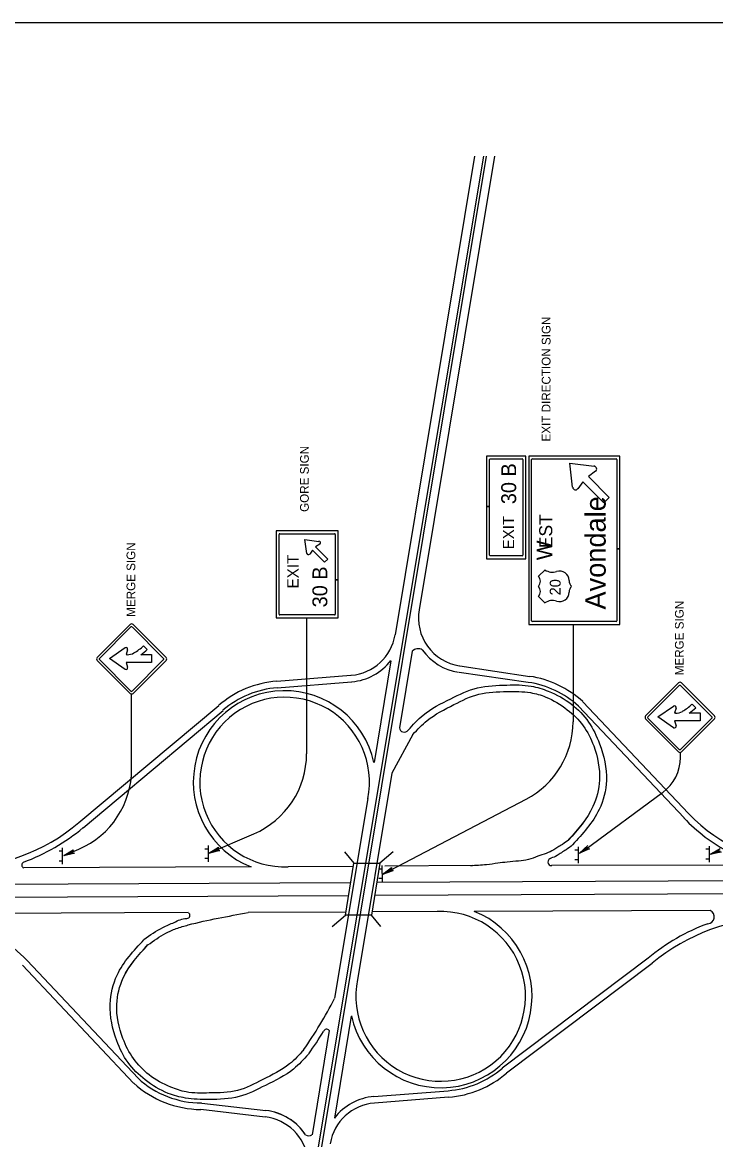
# Model space of a CAD drawing. Extents: x 644898 to 648326, y 298294 to 300670.
# Drawn here: x 645925.8 to 646164.6, y 299676.7 to 300061.5 of the extents above; entities that cross this region are included whole.
import ezdxf

# ---------------------------------------------------------------- set-up
doc = ezdxf.new("R2010")
doc.units = 0
doc.layers.add('1', color=7, linetype='Continuous')
doc.layers.add('2', color=7, linetype='Continuous')

msp = doc.modelspace()

# ---------------------------------------------------------------- linework, layer by layer
at = {"layer": '1'}
msp.add_line((645779.32, 300061.49), (646565.32, 300061.49), dxfattribs=at)
at = {"layer": '2'}
for p, q in [((646084.57, 300015.38), (646006.07, 299544.51)), ((646085.57, 300015.38), (646007.2, 299544.51)), ((646081.57, 300015.38), (646054.2, 299850.51)), ((646088.45, 300015.38), (646062.45, 299859.13)), ((646081.57, 300015.38), (646081.57, 300015.38)), ((646099.2, 299912.13), (646085.7, 299912.13)), ((646085.7, 299912.13), (646085.7, 299894.74)), ((646086.7, 299894.74), (646086.7, 299910.88)), ((646086.95, 299911.13), (646097.95, 299911.13)), ((646098.2, 299910.88), (646098.2, 299878.01)), ((646099.2, 299876.76), (646099.2, 299912.13)), ((646131.57, 299912.13), (646100.2, 299912.13)), ((646100.2, 299912.13), (646100.2, 299854.13)), ((646101.2, 299855.38), (646101.2, 299910.88)), ((646101.45, 299911.13), (646130.32, 299911.13)), ((646115.32, 299901.38), (646114.32, 299909.63)), ((646114.32, 299909.63), (646122.7, 299908.63)), ((646115.32, 299901.38), (646114.32, 299909.63)), ((646114.32, 299909.63), (646122.7, 299908.63)), ((646130.57, 299910.88), (646130.57, 299880.15)), ((646131.57, 299880.15), (646131.57, 299912.13)), ((646123.2, 299906.88), (646120.82, 299905.13)), ((646123.2, 299906.88), (646120.82, 299905.13)), ((646120.82, 299905.13), (646127.95, 299897.88)), ((646120.82, 299905.13), (646127.95, 299897.88)), ((646118.82, 299903.26), (646117.07, 299900.88)), ((646118.82, 299903.26), (646117.07, 299900.88)), ((646126.07, 299896.01), (646118.82, 299903.26)), ((646126.07, 299896.01), (646118.82, 299903.26)), ((646127.95, 299897.88), (646126.07, 299896.01)), ((646127.95, 299897.88), (646126.07, 299896.01)), ((646086.7, 299894.74), (646085.7, 299894.74)), ((646085.7, 299894.74), (646085.7, 299876.76)), ((646085.7, 299894.74), (646086.7, 299894.74)), ((646086.7, 299878.01), (646086.7, 299894.74)), ((646034.57, 299886.38), (646013.2, 299886.38)), ((646013.2, 299886.38), (646013.2, 299856.38)), ((646014.45, 299885.38), (646033.32, 299885.38)), ((646034.57, 299869.44), (646034.57, 299886.38)), ((646014.2, 299857.63), (646014.2, 299885.13)), ((646023.77, 299878.58), (646023.14, 299883.33)), ((646023.14, 299883.33), (646027.89, 299882.71)), ((646028.27, 299881.83), (646026.77, 299880.83)), ((646033.57, 299885.13), (646033.57, 299869.44)), ((646025.77, 299879.71), (646024.77, 299878.33)), ((646029.89, 299875.58), (646025.77, 299879.71)), ((646026.77, 299880.83), (646031.02, 299876.58)), ((646097.95, 299877.76), (646086.95, 299877.76)), ((646130.57, 299880.15), (646131.57, 299880.15)), ((646131.57, 299880.15), (646130.57, 299880.15)), ((646130.57, 299880.15), (646130.57, 299855.38)), ((646131.57, 299854.13), (646131.57, 299880.15)), ((646031.02, 299876.58), (646029.89, 299875.58)), ((646085.7, 299876.76), (646099.2, 299876.76)), ((646103.57, 299870.76), (646105.82, 299872.88)), ((646110.82, 299872.51), (646110.82, 299872.51)), ((646034.57, 299869.44), (646033.57, 299869.44)), ((646033.57, 299869.44), (646033.57, 299857.63)), ((646033.57, 299869.44), (646034.57, 299869.44)), ((646034.57, 299856.38), (646034.57, 299869.44)), ((646109.32, 299867.26), (646109.32, 299867.26)), ((646109.32, 299867.26), (646109.32, 299867.26)), ((646109.32, 299867.26), (646109.32, 299867.26)), ((646109.32, 299867.26), (646109.32, 299867.26)), ((646109.32, 299867.26), (646109.32, 299867.26)), ((646109.32, 299867.26), (646109.32, 299867.26)), ((646111.45, 299869.51), (646111.45, 299869.51)), ((646114.2, 299869.26), (646114.2, 299869.26)), ((646105.82, 299861.51), (646103.57, 299863.76)), ((646114.2, 299865.26), (646114.2, 299865.26)), ((646013.2, 299856.38), (646034.57, 299856.38)), ((646033.32, 299857.38), (646014.45, 299857.38)), ((646023.7, 299856.13), (646023.7, 299809.59)), ((646130.32, 299855.13), (646101.45, 299855.13)), ((645951.57, 299842.76), (645962.95, 299854.13)), ((645952.32, 299842.38), (645963.2, 299853.26)), ((645963.57, 299853.26), (645974.45, 299842.38)), ((645963.95, 299854.13), (645975.32, 299842.76)), ((646100.2, 299854.51), (646100.2, 299854.13)), ((646100.2, 299854.13), (646131.57, 299854.13)), ((646115.45, 299854.01), (646115.45, 299820.57)), ((645955.82, 299842.38), (645961.2, 299846.13)), ((645962.07, 299845.38), (645961.57, 299843.76)), ((645961.57, 299843.76), (645961.95, 299843.76)), ((645966.57, 299843.76), (645970.32, 299843.76)), ((645967.57, 299846.76), (645968.82, 299845.51)), ((645970.32, 299843.76), (645970.32, 299841.01)), ((646060.07, 299844.88), (646055.7, 299818.51)), ((645962.95, 299830.38), (645951.57, 299841.76)), ((645963.2, 299831.13), (645952.32, 299842.01)), ((645961.2, 299838.63), (645955.82, 299842.38)), ((645970.32, 299841.01), (645961.57, 299841.01)), ((645961.57, 299841.01), (645962.07, 299839.38)), ((645974.45, 299842.01), (645963.57, 299831.13)), ((645974.45, 299842.01), (645963.57, 299831.13)), ((645975.32, 299841.76), (645963.95, 299830.38)), ((646052.7, 299841.63), (646046.95, 299806.63)), ((646076.52, 299839.84), (646100.54, 299836.25)), ((646013.4, 299834.57), (646038.95, 299836.6)), ((646100.04, 299834.18), (646076.29, 299837.61)), ((646013.57, 299832.34), (646039.13, 299834.36)), ((646140.45, 299822.63), (646151.82, 299834.01)), ((646141.2, 299822.26), (646152.07, 299833.13)), ((646152.45, 299833.13), (646163.32, 299822.26)), ((646152.82, 299834.01), (646164.2, 299822.63)), ((645963.45, 299804.32), (645963.45, 299830.13)), ((645945.2, 299785.88), (645993.45, 299826.26)), ((645946.7, 299784.13), (645994.95, 299824.51)), ((646153.7, 299787.51), (646117.32, 299826.01)), ((646155.2, 299789.01), (646118.82, 299827.51)), ((646144.7, 299822.26), (646150.07, 299826.01)), ((646150.95, 299825.26), (646150.45, 299823.63)), ((646156.45, 299826.63), (646157.7, 299825.38)), ((646151.82, 299810.26), (646140.45, 299821.63)), ((646152.07, 299811.01), (646141.2, 299821.88)), ((646150.07, 299818.51), (646144.7, 299822.26)), ((646150.45, 299823.63), (646150.82, 299823.63)), ((646159.2, 299820.88), (646150.45, 299820.88)), ((646150.45, 299820.88), (646150.95, 299819.26)), ((646163.32, 299821.88), (646152.45, 299811.01)), ((646163.32, 299821.88), (646152.45, 299811.01)), ((646164.2, 299821.63), (646152.82, 299810.26)), ((646155.45, 299823.63), (646159.2, 299823.63)), ((646159.2, 299823.63), (646159.2, 299820.88)), ((646060.32, 299816.26), (646053.07, 299802.88)), ((646152.45, 299808.32), (646152.45, 299810.01)), ((646053.07, 299802.88), (646041.2, 299731.76)), ((646044.82, 299794.13), (646033.32, 299725.38)), ((646049.95, 299768.13), (646099.36, 299793.99)), ((646119.54, 299776.55), (646146.33, 299796.23)), ((645990.07, 299775.38), (646005.53, 299782.02)), ((645989.82, 299778.01), (645989.82, 299772.38)), ((646162.32, 299777.76), (646162.32, 299772.26)), ((645939.57, 299776.01), (645938.45, 299776.01)), ((645939.57, 299777.13), (645939.57, 299771.51)), ((645940.07, 299774.51), (645945.31, 299776.76)), ((645989.82, 299776.76), (645988.7, 299776.76)), ((646036.7, 299775.76), (646039.95, 299771.88)), ((646053.57, 299775.76), (646048.95, 299771.88)), ((646117.2, 299776.38), (646116.07, 299776.38)), ((646117.2, 299777.51), (646117.2, 299771.88)), ((646162.32, 299776.76), (646161.2, 299776.76)), ((646004.57, 299770.63), (645926.32, 299770.26)), ((645939.57, 299772.63), (645938.45, 299772.63)), ((645989.82, 299773.51), (645988.7, 299773.51)), ((646039.7, 299770.76), (646017.32, 299770.63)), ((646037.07, 299754.01), (646039.95, 299771.88)), ((646039.95, 299771.88), (646048.95, 299771.88)), ((646048.95, 299771.88), (646046.07, 299754.01)), ((646049.57, 299771.13), (646049.7, 299765.51)), ((646080.79, 299771.05), (646050.65, 299770.88)), ((646168.7, 299771.26), (646108.07, 299771.13)), ((646117.2, 299773.01), (646116.07, 299773.01)), ((646162.32, 299773.26), (646161.2, 299773.26)), ((646565.32, 299767.51), (646047.95, 299765.26)), ((646049.7, 299769.88), (646048.57, 299769.88)), ((646049.7, 299766.63), (646048.57, 299766.63)), ((646038.82, 299765.13), (645779.32, 299764.01)), ((646039.95, 299765.13), (646039.95, 299765.13)), ((646046.82, 299765.26), (646046.82, 299765.26)), ((646565.32, 299763.14), (646047.2, 299760.76)), ((646038.07, 299760.63), (645779.32, 299759.51)), ((646039.2, 299760.63), (646039.2, 299760.63)), ((646046.07, 299760.76), (646046.07, 299760.76)), ((645982.95, 299754.88), (645907.2, 299754.51)), ((646037.07, 299755.01), (646003.57, 299754.88)), ((646045.2, 299755.13), (646045.2, 299755.13)), ((646068.7, 299755.26), (646046.32, 299755.13)), ((646162.7, 299755.63), (646081.45, 299755.26)), ((646032.45, 299750.13), (646037.07, 299754.01)), ((646046.07, 299754.01), (646037.07, 299754.01)), ((646049.32, 299750.13), (646046.07, 299754.01)), ((645925.82, 299736.76), (645964.07, 299696.13)), ((645927.45, 299738.38), (645965.7, 299697.88)), ((646141.32, 299739.13), (646091.07, 299701.26)), ((646142.7, 299737.38), (646092.57, 299699.63)), ((646039.07, 299719.26), (646033.32, 299684.13)), ((646031.45, 299714.26), (646025.57, 299678.38)), ((646046.89, 299691.51), (646072.44, 299693.54)), ((645987.57, 299689.26), (646009.7, 299686.76)), ((646072.62, 299691.3), (646047.07, 299689.28)), ((645987.32, 299687.13), (646009.45, 299684.51))]:
    msp.add_line(p, q, dxfattribs=at)
for points in [[(646120.67, 299776.97), (646120.67, 299777.09), (646117.67, 299775.34), (646120.67, 299776.97), (646121.17, 299776.84), (646117.67, 299775.34), (646120.17, 299777.34), (646120.29, 299777.72), (646117.67, 299775.34), (646120.54, 299777.97), (646120.29, 299777.72)], [(645943.45, 299775.38), (645943.32, 299775.51), (645940.07, 299774.51), (645943.45, 299775.38), (645943.82, 299775.38), (645940.07, 299774.51), (645943.2, 299775.88), (645943.2, 299776.13), (645940.07, 299774.51), (645943.32, 299776.51), (645943.2, 299776.13)], [(645993.45, 299776.26), (645993.32, 299776.38), (645990.07, 299775.38), (645993.45, 299776.26), (645993.82, 299776.26), (645990.07, 299775.38), (645993.2, 299776.76), (645993.2, 299777.01), (645990.07, 299775.38), (645993.32, 299777.38), (645993.2, 299777.01)], [(646166.11, 299775.84), (646166.09, 299776.09), (646162.79, 299774.98), (646166.11, 299775.84), (646166.49, 299775.74), (646162.79, 299774.98), (646165.69, 299776.44), (646165.93, 299776.71), (646162.79, 299774.98), (646166.16, 299776.97), (646165.93, 299776.71)], [(646053.2, 299769.26), (646053.07, 299769.38), (646049.95, 299768.13), (646053.2, 299769.26), (646053.57, 299769.38), (646049.95, 299768.13), (646052.95, 299769.76), (646052.95, 299770.01), (646049.95, 299768.13), (646052.95, 299770.38), (646052.95, 299770.01)]]:
    msp.add_lwpolyline(points, dxfattribs=at)
for centre, radius, start, end in [((646086.95, 299910.88), 0.25, 90, 180), ((646097.95, 299910.88), 0.25, 0, 90), ((646101.45, 299910.88), 0.25, 90, 180), ((646122.63, 299907.68), 0.978, 303.2449, 87.1516), ((646122.63, 299907.68), 0.978, 303.2449, 87.1516), ((646130.32, 299910.88), 0.25, 0, 90), ((646116.33, 299901.46), 0.978, 184.8565, 325.522), ((646116.33, 299901.46), 0.978, 184.8565, 325.522), ((646014.45, 299885.13), 0.25, 90, 180), ((646033.32, 299885.13), 0.25, 0, 90), ((646027.91, 299882.26), 0.559, 303.2476, 87.1543), ((646024.31, 299878.7), 0.559, 184.8591, 325.5247), ((646086.95, 299878.01), 0.25, 180, 270), ((646097.95, 299878.01), 0.25, 270, 360), ((646101.28, 299869), 2.93, 323.136, 36.864), ((646108.38, 299876.66), 4.55, 235.4253, 288.1711), ((646110.84, 299869.25), 3.26, 0.0047, 108.548), ((646101.28, 299865.48), 2.93, 323.136, 36.864), ((646116.85, 299869.25), 2.76, 180, 226.2725), ((646116.85, 299865.23), 2.76, 133.7275, 180), ((646108.38, 299857.82), 4.55, 71.8289, 124.5747), ((646110.84, 299865.23), 3.26, 251.452, 359.9953), ((646079.01, 299856.45), 16.8, 170.549, 260.8199), ((646014.45, 299857.63), 0.25, 180, 270), ((646033.32, 299857.63), 0.25, 270, 0), ((646101.45, 299855.38), 0.25, 180, 270), ((646130.32, 299855.38), 0.25, 270, 360), ((645963.46, 299853.62), 0.699, 45, 135), ((645963.39, 299853.09), 0.25, 45, 135), ((646037.62, 299853.34), 16.8, 274.9998, 350.549), ((645961.51, 299845.59), 0.582, 343.7978, 121.6694), ((645961.89, 299848.43), 4.73, 269.7757, 299.8897), ((645956.19, 299858.6), 16.39, 299.437, 313.8849), ((645955.88, 299858.97), 18.68, 305.1415, 313.8892), ((646062.07, 299843.06), 2.71, 56.7513, 138.064), ((646079.01, 299856.45), 19.04, 215.7561, 260.8199), ((645952.09, 299842.25), 0.699, 135, 225), ((645952.49, 299842.2), 0.25, 135, 225), ((645961.51, 299839.18), 0.582, 238.443, 16.0898), ((645974.26, 299842.22), 0.25, 309.2894, 45), ((645974.83, 299842.25), 0.699, 315, 45), ((646037.62, 299853.34), 19.04, 274.9998, 322.4775), ((646095.39, 299801.81), 34.82, 47.6535, 81.4907), ((646016.14, 299799.86), 34.82, 94.5222, 130.6655), ((646016.14, 299799.86), 32.58, 94.5221, 130.7111), ((646095.39, 299801.93), 32.58, 47.6079, 81.7842), ((646152.33, 299833.5), 0.699, 45, 135), ((646152.26, 299832.97), 0.25, 45, 135), ((645963.46, 299830.88), 0.699, 225, 315), ((645963.39, 299831.3), 0.25, 225, 315), ((645963.39, 299831.3), 0.25, 225, 315), ((646016.14, 299799.86), 31.46, 12.3822, 248.4012), ((646016.14, 299799.86), 29.22, 348.5631, 272.42), ((646150.38, 299825.46), 0.582, 343.7978, 121.6694), ((646150.76, 299828.3), 4.73, 269.7757, 299.8897), ((646145.07, 299838.48), 16.39, 299.437, 313.8849), ((646144.75, 299838.85), 18.68, 305.1415, 313.8892), ((646085.45, 299820.57), 30, 297.6198, 0), ((646140.96, 299822.13), 0.699, 135, 225), ((646141.36, 299822.07), 0.25, 135, 225), ((646163.14, 299822.09), 0.25, 309.2894, 45), ((646163.7, 299822.13), 0.699, 315, 45), ((646057.3, 299818.68), 1.65, 185.8754, 324.1731), ((646150.38, 299819.05), 0.582, 238.443, 16.0898), ((645993.7, 299809.59), 30, 293.2274, 0), ((646152.33, 299810.76), 0.699, 225, 315), ((646152.26, 299811.18), 0.25, 225, 315), ((646152.26, 299811.18), 0.25, 225, 315), ((646137.45, 299808.32), 15, 306.3102, 0), ((645933.45, 299804.32), 30, 293.2859, 0), ((645902.12, 299837.34), 67.18, 270.2525, 309.9999), ((646196.02, 299827.44), 58.23, 223.3194, 242.7882), ((646196.02, 299827.44), 55.99, 223.3194, 270.2525), ((645902.12, 299837.34), 69.42, 290.3144, 309.9999), ((645926.68, 299771.27), 1.07, 115.542, 249.178), ((646108.07, 299772.34), 1.28, 97.9214, 271.8942), ((645982.47, 299753.92), 1.05, 268.4832, 60.6541), ((646069.88, 299726.02), 31.46, 192.3822, 68.4017), ((646069.88, 299726.02), 29.22, 168.5632, 92.4201), ((646161.77, 299753.44), 2.38, 271.8811, 66.8776), ((645885.05, 299698.42), 58.23, 43.3195, 67.8501), ((646185.95, 299685.96), 69.42, 110.3144, 130), ((646185.95, 299685.96), 67.18, 90.2526, 130), ((645898.14, 299794.72), 151.98, 325.0122, 332.8209), ((645898.14, 299794.72), 154.22, 325.0122, 328.4086), ((646030.58, 299713.58), 1.14, 36.3436, 162.0571), ((646069.88, 299726.02), 32.58, 274.5223, 310.7112), ((645987.6, 299721.89), 32.58, 227.608, 269.9111), ((646069.88, 299726.02), 34.82, 274.5221, 310.6656), ((645987.6, 299721.89), 34.82, 227.6536, 269.4877), ((646048.39, 299672.54), 16.8, 94.522, 170.549), ((646048.39, 299672.54), 19.04, 94.5222, 142.4776), ((646007.5, 299667.8), 19.04, 35.8416, 83.3193), ((646007.5, 299667.8), 19.04, 33.5325, 83.3193), ((646007.5, 299667.8), 16.8, 7.7701, 83.3193), ((646024.41, 299679.75), 1.77, 234.1369, 309.4414)]:
    msp.add_arc(centre, radius, start, end, dxfattribs=at)
for points in [[(646058.7, 299817.76), (646063.82, 299822.88), (646073.32, 299828.51), (646082.57, 299832.26), (646092.7, 299833.26), (646101.07, 299832.88), (646106.95, 299831.13), (646114.95, 299826.63), (646120.82, 299820.51), (646124.57, 299813.01), (646126.95, 299800.38), (646124.45, 299790.38), (646115.32, 299778.26)], [(646060.32, 299816.26), (646065.2, 299821.01), (646074.45, 299826.51), (646083.07, 299830.13), (646092.7, 299831.01), (646100.82, 299830.63), (646106.07, 299829.13), (646113.45, 299824.76), (646118.95, 299819.26), (646122.57, 299812.26), (646124.57, 299800.51), (646122.32, 299791.38), (646113.95, 299780.01)], [(646060.32, 299816.26), (646065.2, 299821.01), (646074.45, 299826.51), (646083.07, 299830.13), (646092.7, 299831.01), (646100.82, 299830.63), (646106.07, 299829.13), (646113.45, 299824.76), (646118.95, 299819.26), (646122.57, 299812.26), (646124.57, 299800.51), (646122.32, 299791.38), (646113.95, 299779.88)], [(646113.95, 299779.88), (646111.82, 299778.38), (646110.2, 299777.38), (646108.82, 299776.51), (646106.2, 299775.26), (646103.32, 299774.26), (646100.07, 299773.13), (646096.7, 299772.63), (646092.82, 299772.26), (646089.57, 299771.88), (646085.7, 299771.38), (646080.2, 299771.01)], [(646115.32, 299778.26), (646113.07, 299776.51), (646111.45, 299775.51), (646109.95, 299774.51), (646107.82, 299773.63)], [(645969.07, 299743.76), (645975.2, 299747.76), (645978.82, 299749.38), (645982.95, 299750.63), (646003.57, 299754.88)], [(645967.7, 299745.63), (645974.2, 299749.76), (645978.07, 299751.51), (645982.32, 299752.88), (645982.45, 299752.88)], [(646024.32, 299706.13), (646019.2, 299701.01), (646009.57, 299695.38), (646000.45, 299691.51), (645990.2, 299690.51), (645981.95, 299691.01), (645976.07, 299692.63), (645968.07, 299697.26), (645962.2, 299703.26), (645958.32, 299710.76), (645956.07, 299723.38), (645958.45, 299733.38), (645967.7, 299745.51)], [(646022.7, 299707.51), (646017.82, 299702.76), (646008.57, 299697.38), (645999.95, 299693.63), (645990.2, 299692.76), (645982.2, 299693.13), (645976.95, 299694.76), (645969.45, 299699.01), (645964.07, 299704.63), (645960.45, 299711.51), (645958.32, 299723.26), (645960.57, 299732.38), (645969.07, 299743.88)], [(646022.7, 299707.51), (646017.82, 299702.76), (646008.57, 299697.38), (645999.95, 299693.63), (645990.2, 299692.76), (645982.2, 299693.13), (645976.95, 299694.76), (645969.45, 299699.01), (645964.07, 299704.63), (645960.45, 299711.51), (645958.32, 299723.26), (645960.57, 299732.38), (645969.07, 299743.76)]]:
    msp.add_spline(points, degree=3, dxfattribs=at)

# ---------------------------------------------------------------- texts
for s, height, rotation, p in [('EXIT DIRECTION SIGN', 3, 90, (646107.7, 299917.13)), ('GORE SIGN', 3, 90, (646024.45, 299892.88)), ('30 B', 5.125, 90, (646095.87, 299895.55)), ('Avondale', 7, 89.9998, (646126.7, 299859.26)), ('EXIT', 3.875, 90, (646095.16, 299880)), ('EST', 4.5, 90, (646108.32, 299880.38)), ('MERGE SIGN', 3, 90, (645964.7, 299856.76)), ('W', 5.38, 90, (646108.32, 299876.26)), ('EXIT', 3.917, 90, (646020.95, 299866.51)), ('30 B', 5.125, 90, (646030.83, 299860.01)), ('20', 3.75, 90, (646111.2, 299864.13)), ('MERGE SIGN', 3, 90, (646153.57, 299836.63))]:
    msp.add_text(s, height=height, rotation=rotation, dxfattribs=at).set_placement(p)

doc.saveas('drawing.dxf')
